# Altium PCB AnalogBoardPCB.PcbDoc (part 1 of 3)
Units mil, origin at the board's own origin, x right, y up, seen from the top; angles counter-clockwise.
Board outline 5875 x 2550 mil, 4 copper layers (Top Layer, GND, VCC, Bottom Layer); 569 components, 22 nets, 1336 pads, 360 vias.
Unrouted connection lines stored in the file: 31.
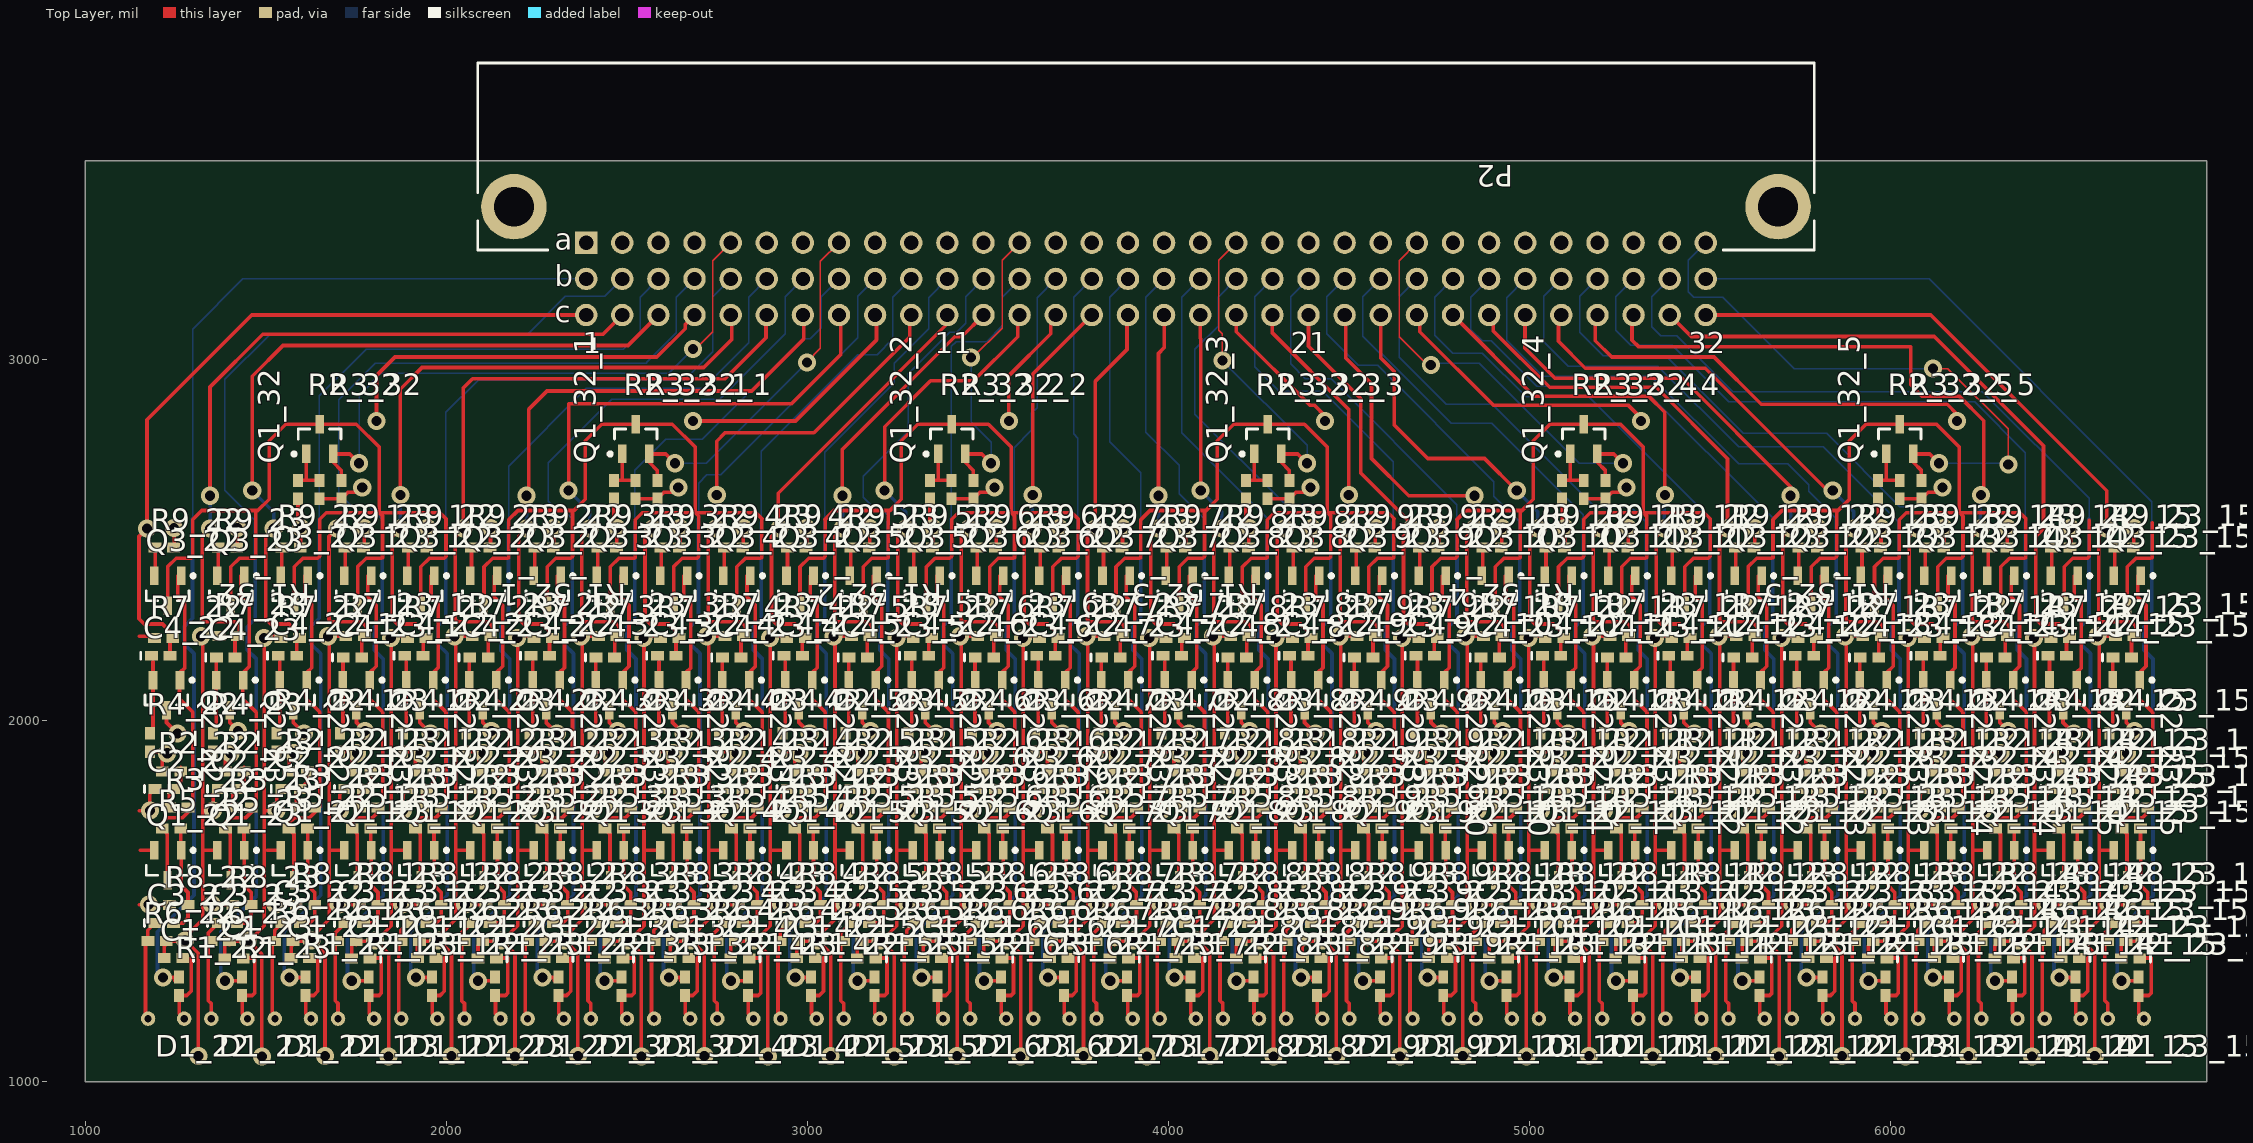
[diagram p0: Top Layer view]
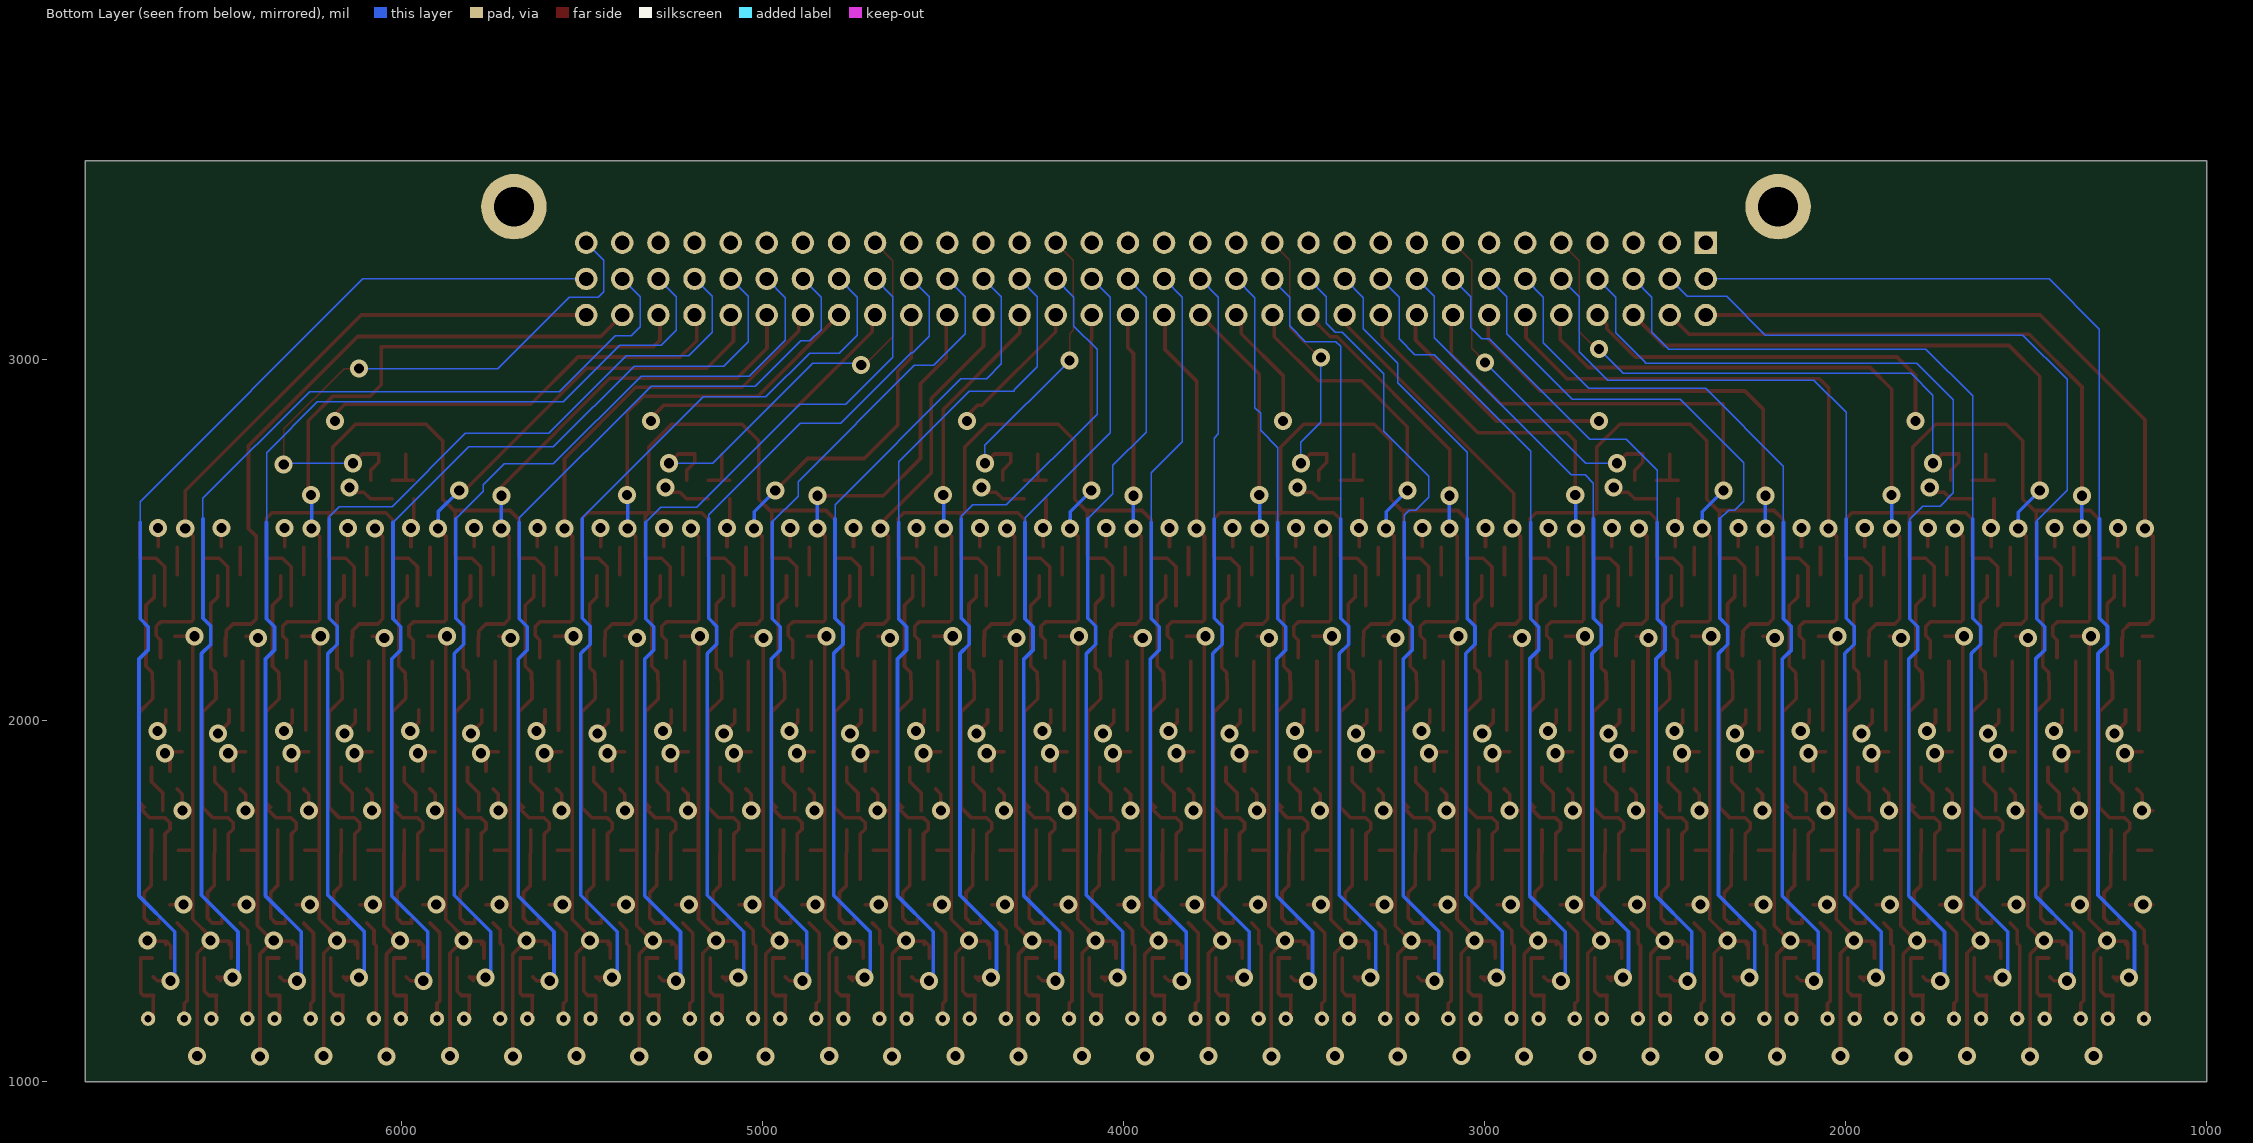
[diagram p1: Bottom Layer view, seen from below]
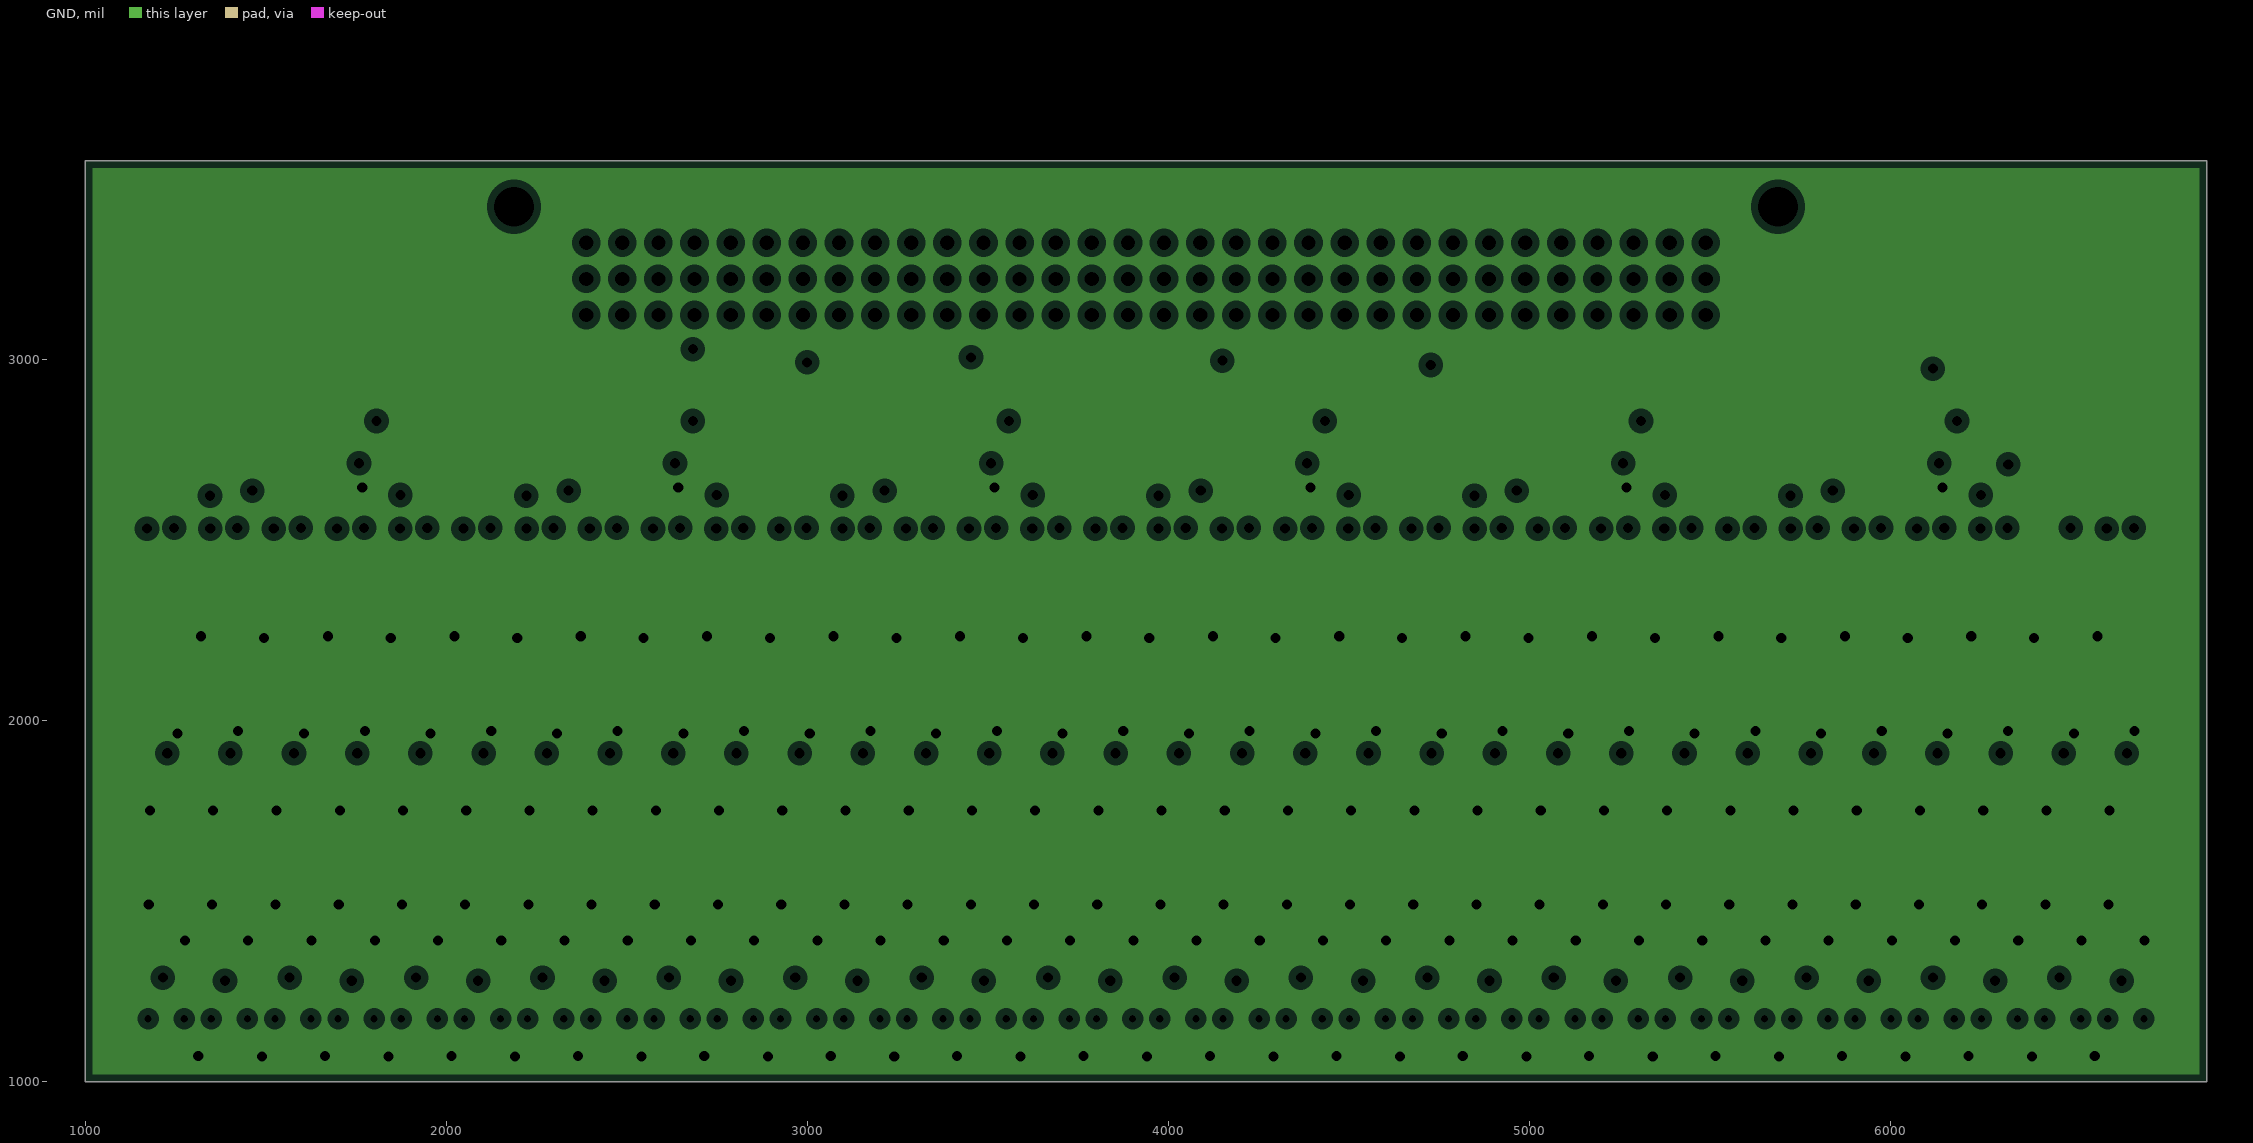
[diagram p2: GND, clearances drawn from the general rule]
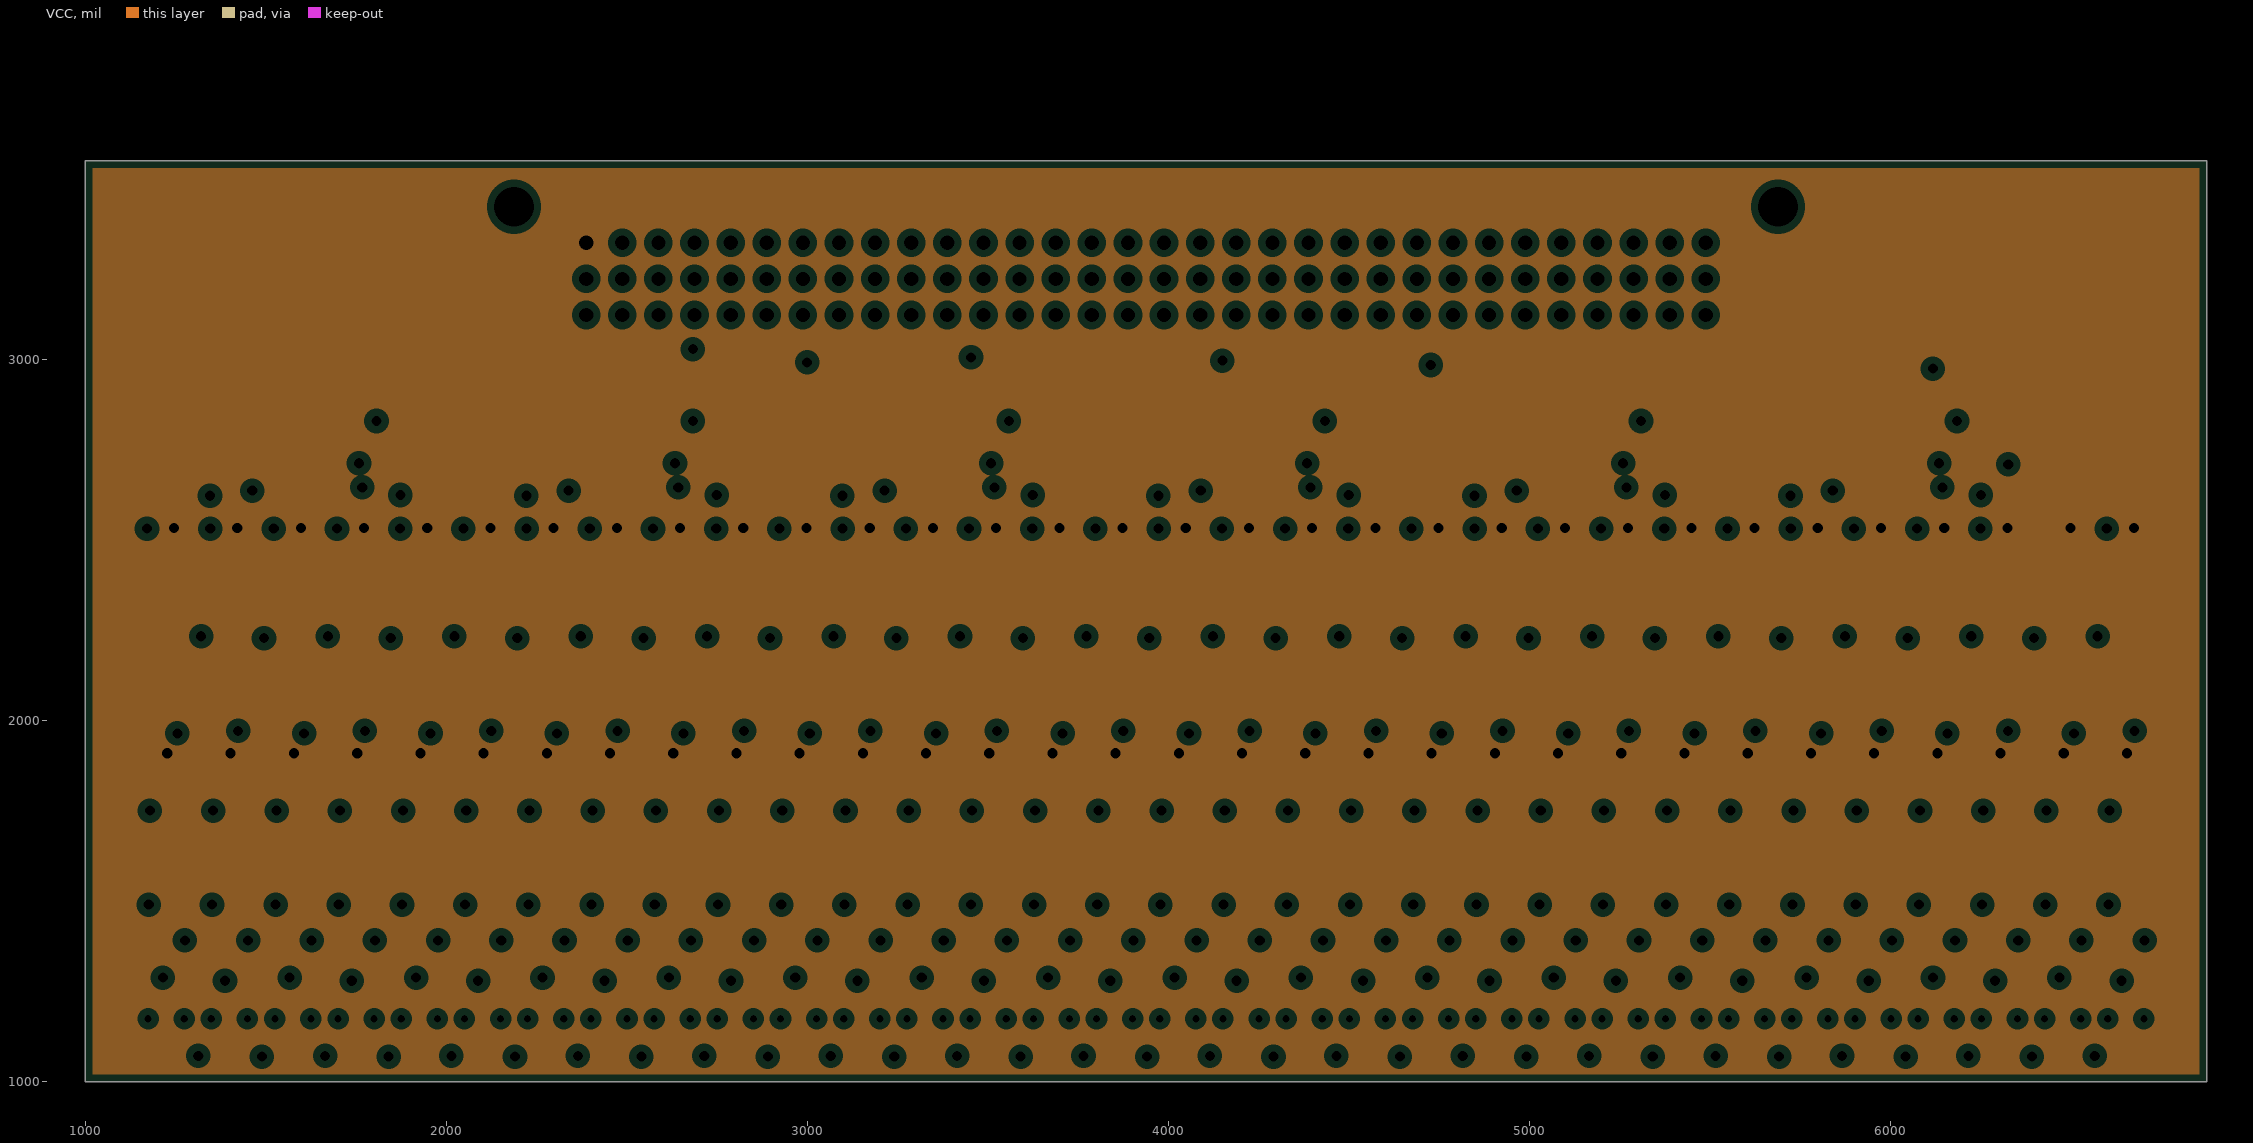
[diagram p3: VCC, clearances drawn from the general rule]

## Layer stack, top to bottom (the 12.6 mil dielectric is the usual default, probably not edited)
Top Layer: signal copper 1.4
Dielectric: core 12.6, FR-4, Dk 4.8
GND: plane copper 1.4, net GND
Dielectric: prepreg 12.6, FR-4, Dk 4.8
VCC: plane copper 1.4, net VCC
Dielectric: core 12.6, FR-4, Dk 4.8
Bottom Layer: signal copper 1.4

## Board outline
1000,1000 6875,1000 6875,3550 1000,3550

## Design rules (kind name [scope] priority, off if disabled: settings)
Clearance biasvoltages [InNet('SIPMBIAS1')] p1: gap=15
Clearance [All] p2: gap=10
ComponentClearance [All] p1: gap=10 collisioncheckmode=3 verticalgap=10
PlaneClearance [All] p1: clearance=20
PlaneConnect [All] p1: planeconnectstyle=Relief reliefexpansion=20 reliefentries=4 reliefconductorwidth=10 reliefairgap=10
PolygonConnect [All] p1: connectstyle=Relief reliefconductorwidth=10 reliefentries=4 polygonreliefangle="90 Angle"
RoutingVias [All] p1: holewidth=28 width=50 viastyle="Through Hole" minholewidth=28 minwidth=50 maxholewidth=28 maxwidth=50
ShortCircuit ShortCircuitEurocard [InComponent(P2)] p1: allowed=TRUE
ShortCircuit [All] p2: allowed=FALSE
SolderMaskExpansion [All] p1: expansion=4
TestPointUsage [All] p1: valid=0 allowmultiple=FALSE
Testpoint [All] p1: side=15 testpointundercomponent=TRUE minsize=40 maxsize=100 preferedsize=60 minholesize=0 maxholesize=40 preferedholesize=32 testpointgrid=1 style=1023 order=0-112345678
Width [All] p1: maxlimit=10 minlimit=1 preferedwidth=4
15 further rules are at their usual default settings.

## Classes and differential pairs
component class Amplifier1: C1 C2 C3 C4 D1 Q1 Q2 Q3 R1 R2 R3 R4 R5 R6 R7 R8 R9

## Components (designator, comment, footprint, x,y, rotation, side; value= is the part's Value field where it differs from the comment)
C1_22 "Cap" 0402 1245.09,1342 r180 top (schematic designator C1)
C1_22_1 "Cap" 0402 1596.09,1342 r180 top (schematic designator C1)
C1_22_2 "Cap" 0402 1946.09,1342 r180 top (schematic designator C1)
C1_22_3 "Cap" 0402 2296.09,1342 r180 top (schematic designator C1)
C1_22_4 "Cap" 0402 2646.09,1342 r180 top (schematic designator C1)
C1_22_5 "Cap" 0402 2996.09,1342 r180 top (schematic designator C1)
C1_22_6 "Cap" 0402 3346.09,1342 r180 top (schematic designator C1)
C1_22_7 "Cap" 0402 3696.09,1342 r180 top (schematic designator C1)
C1_22_8 "Cap" 0402 4046.09,1342 r180 top (schematic designator C1)
C1_22_9 "Cap" 0402 4396.09,1342 r180 top (schematic designator C1)
C1_22_10 "Cap" 0402 4746.09,1342 r180 top (schematic designator C1)
C1_22_11 "Cap" 0402 5096.09,1342 r180 top (schematic designator C1)
C1_22_12 "Cap" 0402 5446.09,1342 r180 top (schematic designator C1)
C1_22_13 "Cap" 0402 5796.09,1342 r180 top (schematic designator C1)
C1_22_14 "Cap" 0402 6146.09,1342 r180 top (schematic designator C1)
C1_22_15 "Cap" 0402 6496.09,1342 r180 top (schematic designator C1)
C1_23 "Cap" 0402 1412.5,1341 r180 top (schematic designator C1)
C1_23_1 "Cap" 0402 1763.5,1341 r180 top (schematic designator C1)
C1_23_2 "Cap" 0402 2113.5,1341 r180 top (schematic designator C1)
C1_23_3 "Cap" 0402 2463.5,1341 r180 top (schematic designator C1)
C1_23_4 "Cap" 0402 2813.5,1341 r180 top (schematic designator C1)
C1_23_5 "Cap" 0402 3163.5,1341 r180 top (schematic designator C1)
C1_23_6 "Cap" 0402 3513.5,1341 r180 top (schematic designator C1)
C1_23_7 "Cap" 0402 3863.5,1341 r180 top (schematic designator C1)
C1_23_8 "Cap" 0402 4213.5,1341 r180 top (schematic designator C1)
C1_23_9 "Cap" 0402 4563.5,1341 r180 top (schematic designator C1)
C1_23_10 "Cap" 0402 4913.5,1341 r180 top (schematic designator C1)
C1_23_11 "Cap" 0402 5263.5,1341 r180 top (schematic designator C1)
C1_23_12 "Cap" 0402 5613.5,1341 r180 top (schematic designator C1)
C1_23_13 "Cap" 0402 5963.5,1341 r180 top (schematic designator C1)
C1_23_14 "Cap" 0402 6313.5,1341 r180 top (schematic designator C1)
C1_23_15 "Cap" 0402 6663.5,1341 r180 top (schematic designator C1)
C2_22 "Cap" 0402 1219.5,1810 r0 top (schematic designator C2)
C2_22_1 "Cap" 0402 1570.5,1810 r0 top (schematic designator C2)
C2_22_2 "Cap" 0402 1920.5,1810 r0 top (schematic designator C2)
C2_22_3 "Cap" 0402 2270.5,1810 r0 top (schematic designator C2)
C2_22_4 "Cap" 0402 2620.5,1810 r0 top (schematic designator C2)
C2_22_5 "Cap" 0402 2970.5,1810 r0 top (schematic designator C2)
C2_22_6 "Cap" 0402 3320.5,1810 r0 top (schematic designator C2)
C2_22_7 "Cap" 0402 3670.5,1810 r0 top (schematic designator C2)
C2_22_8 "Cap" 0402 4020.5,1810 r0 top (schematic designator C2)
C2_22_9 "Cap" 0402 4370.5,1810 r0 top (schematic designator C2)
C2_22_10 "Cap" 0402 4720.5,1810 r0 top (schematic designator C2)
C2_22_11 "Cap" 0402 5070.5,1810 r0 top (schematic designator C2)
C2_22_12 "Cap" 0402 5420.5,1810 r0 top (schematic designator C2)
C2_22_13 "Cap" 0402 5770.5,1810 r0 top (schematic designator C2)
C2_22_14 "Cap" 0402 6120.5,1810 r0 top (schematic designator C2)
C2_22_15 "Cap" 0402 6470.5,1810 r0 top (schematic designator C2)
C2_23 "Cap" 0402 1394.5,1810 r0 top (schematic designator C2)
C2_23_1 "Cap" 0402 1745.5,1810 r0 top (schematic designator C2)
C2_23_2 "Cap" 0402 2095.5,1810 r0 top (schematic designator C2)
C2_23_3 "Cap" 0402 2445.5,1810 r0 top (schematic designator C2)
C2_23_4 "Cap" 0402 2795.5,1810 r0 top (schematic designator C2)
C2_23_5 "Cap" 0402 3145.5,1810 r0 top (schematic designator C2)
C2_23_6 "Cap" 0402 3495.5,1810 r0 top (schematic designator C2)
C2_23_7 "Cap" 0402 3845.5,1810 r0 top (schematic designator C2)
C2_23_8 "Cap" 0402 4195.5,1810 r0 top (schematic designator C2)
C2_23_9 "Cap" 0402 4545.5,1810 r0 top (schematic designator C2)
C2_23_10 "Cap" 0402 4895.5,1810 r0 top (schematic designator C2)
C2_23_11 "Cap" 0402 5245.5,1810 r0 top (schematic designator C2)
C2_23_12 "Cap" 0402 5595.5,1810 r0 top (schematic designator C2)
C2_23_13 "Cap" 0402 5945.5,1810 r0 top (schematic designator C2)
C2_23_14 "Cap" 0402 6295.5,1810 r0 top (schematic designator C2)
C2_23_15 "Cap" 0402 6645.5,1810 r0 top (schematic designator C2)
C3_22 "Cap" 0402 1219.5,1439 r0 top (schematic designator C3)
C3_22_1 "Cap" 0402 1570.5,1439 r0 top (schematic designator C3)
C3_22_2 "Cap" 0402 1920.5,1439 r0 top (schematic designator C3)
C3_22_3 "Cap" 0402 2270.5,1439 r0 top (schematic designator C3)
C3_22_4 "Cap" 0402 2620.5,1439 r0 top (schematic designator C3)
C3_22_5 "Cap" 0402 2970.5,1439 r0 top (schematic designator C3)
C3_22_6 "Cap" 0402 3320.5,1439 r0 top (schematic designator C3)
C3_22_7 "Cap" 0402 3670.5,1439 r0 top (schematic designator C3)
C3_22_8 "Cap" 0402 4020.5,1439 r0 top (schematic designator C3)
C3_22_9 "Cap" 0402 4370.5,1439 r0 top (schematic designator C3)
C3_22_10 "Cap" 0402 4720.5,1439 r0 top (schematic designator C3)
C3_22_11 "Cap" 0402 5070.5,1439 r0 top (schematic designator C3)
C3_22_12 "Cap" 0402 5420.5,1439 r0 top (schematic designator C3)
C3_22_13 "Cap" 0402 5770.5,1439 r0 top (schematic designator C3)
C3_22_14 "Cap" 0402 6120.5,1439 r0 top (schematic designator C3)
C3_22_15 "Cap" 0402 6470.5,1439 r0 top (schematic designator C3)
C3_23 "Cap" 0402 1394.5,1439 r0 top (schematic designator C3)
C3_23_1 "Cap" 0402 1745.5,1439 r0 top (schematic designator C3)
C3_23_2 "Cap" 0402 2095.5,1439 r0 top (schematic designator C3)
C3_23_3 "Cap" 0402 2445.5,1439 r0 top (schematic designator C3)
C3_23_4 "Cap" 0402 2795.5,1439 r0 top (schematic designator C3)
C3_23_5 "Cap" 0402 3145.5,1439 r0 top (schematic designator C3)
C3_23_6 "Cap" 0402 3495.5,1439 r0 top (schematic designator C3)
C3_23_7 "Cap" 0402 3845.5,1439 r0 top (schematic designator C3)
C3_23_8 "Cap" 0402 4195.5,1439 r0 top (schematic designator C3)
C3_23_9 "Cap" 0402 4545.5,1439 r0 top (schematic designator C3)
C3_23_10 "Cap" 0402 4895.5,1439 r0 top (schematic designator C3)
C3_23_11 "Cap" 0402 5245.5,1439 r0 top (schematic designator C3)
C3_23_12 "Cap" 0402 5595.5,1439 r0 top (schematic designator C3)
C3_23_13 "Cap" 0402 5945.5,1439 r0 top (schematic designator C3)
C3_23_14 "Cap" 0402 6295.5,1439 r0 top (schematic designator C3)
C3_23_15 "Cap" 0402 6645.5,1439 r0 top (schematic designator C3)
C4_22 "Cap" 0402 1209.5,2179 r0 top (schematic designator C4)
C4_22_1 "Cap" 0402 1560.5,2179 r0 top (schematic designator C4)
C4_22_2 "Cap" 0402 1910.5,2179 r0 top (schematic designator C4)
C4_22_3 "Cap" 0402 2260.5,2179 r0 top (schematic designator C4)
C4_22_4 "Cap" 0402 2610.5,2179 r0 top (schematic designator C4)
C4_22_5 "Cap" 0402 2960.5,2179 r0 top (schematic designator C4)
C4_22_6 "Cap" 0402 3310.5,2179 r0 top (schematic designator C4)
C4_22_7 "Cap" 0402 3660.5,2179 r0 top (schematic designator C4)
C4_22_8 "Cap" 0402 4010.5,2179 r0 top (schematic designator C4)
C4_22_9 "Cap" 0402 4360.5,2179 r0 top (schematic designator C4)
C4_22_10 "Cap" 0402 4710.5,2179 r0 top (schematic designator C4)
C4_22_11 "Cap" 0402 5060.5,2179 r0 top (schematic designator C4)
C4_22_12 "Cap" 0402 5410.5,2179 r0 top (schematic designator C4)
C4_22_13 "Cap" 0402 5760.5,2179 r0 top (schematic designator C4)
C4_22_14 "Cap" 0402 6110.5,2179 r0 top (schematic designator C4)
C4_22_15 "Cap" 0402 6460.5,2179 r0 top (schematic designator C4)
C4_23 "Cap" 0402 1389.5,2174 r0 top (schematic designator C4)
C4_23_1 "Cap" 0402 1740.5,2174 r0 top (schematic designator C4)
C4_23_2 "Cap" 0402 2090.5,2174 r0 top (schematic designator C4)
C4_23_3 "Cap" 0402 2440.5,2174 r0 top (schematic designator C4)
C4_23_4 "Cap" 0402 2790.5,2174 r0 top (schematic designator C4)
C4_23_5 "Cap" 0402 3140.5,2174 r0 top (schematic designator C4)
C4_23_6 "Cap" 0402 3490.5,2174 r0 top (schematic designator C4)
C4_23_7 "Cap" 0402 3840.5,2174 r0 top (schematic designator C4)
C4_23_8 "Cap" 0402 4190.5,2174 r0 top (schematic designator C4)
C4_23_9 "Cap" 0402 4540.5,2174 r0 top (schematic designator C4)
C4_23_10 "Cap" 0402 4890.5,2174 r0 top (schematic designator C4)
C4_23_11 "Cap" 0402 5240.5,2174 r0 top (schematic designator C4)
C4_23_12 "Cap" 0402 5590.5,2174 r0 top (schematic designator C4)
C4_23_13 "Cap" 0402 5940.5,2174 r0 top (schematic designator C4)
C4_23_14 "Cap" 0402 6290.5,2174 r0 top (schematic designator C4)
C4_23_15 "Cap" 0402 6640.5,2174 r0 top (schematic designator C4)
D1_22 "SiPM" "Photonique SiPM" 1224.5,1124 r0 top (schematic designator D1)
D1_22_1 "SiPM" "Photonique SiPM" 1575.5,1124 r0 top (schematic designator D1)
D1_22_2 "SiPM" "Photonique SiPM" 1925.5,1124 r0 top (schematic designator D1)
D1_22_3 "SiPM" "Photonique SiPM" 2275.5,1124 r0 top (schematic designator D1)
D1_22_4 "SiPM" "Photonique SiPM" 2625.5,1124 r0 top (schematic designator D1)
D1_22_5 "SiPM" "Photonique SiPM" 2975.5,1124 r0 top (schematic designator D1)
D1_22_6 "SiPM" "Photonique SiPM" 3325.5,1124 r0 top (schematic designator D1)
D1_22_7 "SiPM" "Photonique SiPM" 3675.5,1124 r0 top (schematic designator D1)
D1_22_8 "SiPM" "Photonique SiPM" 4025.5,1124 r0 top (schematic designator D1)
D1_22_9 "SiPM" "Photonique SiPM" 4375.5,1124 r0 top (schematic designator D1)
D1_22_10 "SiPM" "Photonique SiPM" 4725.5,1124 r0 top (schematic designator D1)
D1_22_11 "SiPM" "Photonique SiPM" 5075.5,1124 r0 top (schematic designator D1)
D1_22_12 "SiPM" "Photonique SiPM" 5425.5,1124 r0 top (schematic designator D1)
D1_22_13 "SiPM" "Photonique SiPM" 5775.5,1124 r0 top (schematic designator D1)
D1_22_14 "SiPM" "Photonique SiPM" 6125.5,1124 r0 top (schematic designator D1)
D1_22_15 "SiPM" "Photonique SiPM" 6475.5,1124 r0 top (schematic designator D1)
D1_23 "SiPM" "Photonique SiPM" 1399.5,1124 r0 top (schematic designator D1)
D1_23_1 "SiPM" "Photonique SiPM" 1750.5,1124 r0 top (schematic designator D1)
D1_23_2 "SiPM" "Photonique SiPM" 2100.5,1124 r0 top (schematic designator D1)
D1_23_3 "SiPM" "Photonique SiPM" 2450.5,1124 r0 top (schematic designator D1)
D1_23_4 "SiPM" "Photonique SiPM" 2800.5,1124 r0 top (schematic designator D1)
D1_23_5 "SiPM" "Photonique SiPM" 3150.5,1124 r0 top (schematic designator D1)
D1_23_6 "SiPM" "Photonique SiPM" 3500.5,1124 r0 top (schematic designator D1)
D1_23_7 "SiPM" "Photonique SiPM" 3850.5,1124 r0 top (schematic designator D1)
D1_23_8 "SiPM" "Photonique SiPM" 4200.5,1124 r0 top (schematic designator D1)
D1_23_9 "SiPM" "Photonique SiPM" 4550.5,1124 r0 top (schematic designator D1)
D1_23_10 "SiPM" "Photonique SiPM" 4900.5,1124 r0 top (schematic designator D1)
D1_23_11 "SiPM" "Photonique SiPM" 5250.5,1124 r0 top (schematic designator D1)
D1_23_12 "SiPM" "Photonique SiPM" 5600.5,1124 r0 top (schematic designator D1)
D1_23_13 "SiPM" "Photonique SiPM" 5950.5,1124 r0 top (schematic designator D1)
D1_23_14 "SiPM" "Photonique SiPM" 6300.5,1124 r0 top (schematic designator D1)
D1_23_15 "SiPM" "Photonique SiPM" 6650.5,1124 r0 top (schematic designator D1)
P2 "DIN41612 48 Connector" EURO2.54-2H96 3937.5,3820 r0 top
Q1_22 "BFS17A" SOT23_N 1228.5,1599 r270 top (schematic designator Q1)
Q1_22_1 "BFS17A" SOT23_N 1579.5,1599 r270 top (schematic designator Q1)
Q1_22_2 "BFS17A" SOT23_N 1929.5,1599 r270 top (schematic designator Q1)
Q1_22_3 "BFS17A" SOT23_N 2279.5,1599 r270 top (schematic designator Q1)
Q1_22_4 "BFS17A" SOT23_N 2629.5,1599 r270 top (schematic designator Q1)
Q1_22_5 "BFS17A" SOT23_N 2979.5,1599 r270 top (schematic designator Q1)
Q1_22_6 "BFS17A" SOT23_N 3329.5,1599 r270 top (schematic designator Q1)
Q1_22_7 "BFS17A" SOT23_N 3679.5,1599 r270 top (schematic designator Q1)
Q1_22_8 "BFS17A" SOT23_N 4029.5,1599 r270 top (schematic designator Q1)
Q1_22_9 "BFS17A" SOT23_N 4379.5,1599 r270 top (schematic designator Q1)
Q1_22_10 "BFS17A" SOT23_N 4729.5,1599 r270 top (schematic designator Q1)
Q1_22_11 "BFS17A" SOT23_N 5079.5,1599 r270 top (schematic designator Q1)
Q1_22_12 "BFS17A" SOT23_N 5429.5,1599 r270 top (schematic designator Q1)
Q1_22_13 "BFS17A" SOT23_N 5779.5,1599 r270 top (schematic designator Q1)
Q1_22_14 "BFS17A" SOT23_N 6129.5,1599 r270 top (schematic designator Q1)
Q1_22_15 "BFS17A" SOT23_N 6479.5,1599 r270 top (schematic designator Q1)
Q1_23 "BFS17A" SOT23_N 1403.5,1599 r270 top (schematic designator Q1)
Q1_23_1 "BFS17A" SOT23_N 1754.5,1599 r270 top (schematic designator Q1)
Q1_23_2 "BFS17A" SOT23_N 2104.5,1599 r270 top (schematic designator Q1)
Q1_23_3 "BFS17A" SOT23_N 2454.5,1599 r270 top (schematic designator Q1)
Q1_23_4 "BFS17A" SOT23_N 2804.5,1599 r270 top (schematic designator Q1)
Q1_23_5 "BFS17A" SOT23_N 3154.5,1599 r270 top (schematic designator Q1)
Q1_23_6 "BFS17A" SOT23_N 3504.5,1599 r270 top (schematic designator Q1)
Q1_23_7 "BFS17A" SOT23_N 3854.5,1599 r270 top (schematic designator Q1)
Q1_23_8 "BFS17A" SOT23_N 4204.5,1599 r270 top (schematic designator Q1)
Q1_23_9 "BFS17A" SOT23_N 4554.5,1599 r270 top (schematic designator Q1)
Q1_23_10 "BFS17A" SOT23_N 4904.5,1599 r270 top (schematic designator Q1)
Q1_23_11 "BFS17A" SOT23_N 5254.5,1599 r270 top (schematic designator Q1)
Q1_23_12 "BFS17A" SOT23_N 5604.5,1599 r270 top (schematic designator Q1)
Q1_23_13 "BFS17A" SOT23_N 5954.5,1599 r270 top (schematic designator Q1)
Q1_23_14 "BFS17A" SOT23_N 6304.5,1599 r270 top (schematic designator Q1)
Q1_23_15 "BFS17A" SOT23_N 6654.5,1599 r270 top (schematic designator Q1)
Q1_32 "BFS17A" SOT23_N 1649.5,2779 r90 top (schematic designator Q1)
Q1_32_1 "BFS17A" SOT23_N 2524.5,2779 r90 top (schematic designator Q1)
Q1_32_2 "BFS17A" SOT23_N 3399.5,2779 r90 top (schematic designator Q1)
Q1_32_3 "BFS17A" SOT23_N 4274.5,2779 r90 top (schematic designator Q1)
Q1_32_4 "BFS17A" SOT23_N 5149.5,2779 r90 top (schematic designator Q1)
Q1_32_5 "BFS17A" SOT23_N 6024.5,2779 r90 top (schematic designator Q1)
Q2_22 "BFT92" SOT23_N 1225.5,2070 r270 top (schematic designator Q2)
Q2_22_1 "BFT92" SOT23_N 1576.5,2070 r270 top (schematic designator Q2)
Q2_22_2 "BFT92" SOT23_N 1926.5,2070 r270 top (schematic designator Q2)
Q2_22_3 "BFT92" SOT23_N 2276.5,2070 r270 top (schematic designator Q2)
Q2_22_4 "BFT92" SOT23_N 2626.5,2070 r270 top (schematic designator Q2)
Q2_22_5 "BFT92" SOT23_N 2976.5,2070 r270 top (schematic designator Q2)
Q2_22_6 "BFT92" SOT23_N 3326.5,2070 r270 top (schematic designator Q2)
Q2_22_7 "BFT92" SOT23_N 3676.5,2070 r270 top (schematic designator Q2)
Q2_22_8 "BFT92" SOT23_N 4026.5,2070 r270 top (schematic designator Q2)
Q2_22_9 "BFT92" SOT23_N 4376.5,2070 r270 top (schematic designator Q2)
Q2_22_10 "BFT92" SOT23_N 4726.5,2070 r270 top (schematic designator Q2)
Q2_22_11 "BFT92" SOT23_N 5076.5,2070 r270 top (schematic designator Q2)
Q2_22_12 "BFT92" SOT23_N 5426.5,2070 r270 top (schematic designator Q2)
Q2_22_13 "BFT92" SOT23_N 5776.5,2070 r270 top (schematic designator Q2)
Q2_22_14 "BFT92" SOT23_N 6126.5,2070 r270 top (schematic designator Q2)
Q2_22_15 "BFT92" SOT23_N 6476.5,2070 r270 top (schematic designator Q2)
Q2_23 "BFT92" SOT23_N 1400.5,2070 r270 top (schematic designator Q2)
Q2_23_1 "BFT92" SOT23_N 1751.5,2070 r270 top (schematic designator Q2)
Q2_23_2 "BFT92" SOT23_N 2101.5,2070 r270 top (schematic designator Q2)
Q2_23_3 "BFT92" SOT23_N 2451.5,2070 r270 top (schematic designator Q2)
Q2_23_4 "BFT92" SOT23_N 2801.5,2070 r270 top (schematic designator Q2)
Q2_23_5 "BFT92" SOT23_N 3151.5,2070 r270 top (schematic designator Q2)
Q2_23_6 "BFT92" SOT23_N 3501.5,2070 r270 top (schematic designator Q2)
Q2_23_7 "BFT92" SOT23_N 3851.5,2070 r270 top (schematic designator Q2)
Q2_23_8 "BFT92" SOT23_N 4201.5,2070 r270 top (schematic designator Q2)
Q2_23_9 "BFT92" SOT23_N 4551.5,2070 r270 top (schematic designator Q2)
Q2_23_10 "BFT92" SOT23_N 4901.5,2070 r270 top (schematic designator Q2)
Q2_23_11 "BFT92" SOT23_N 5251.5,2070 r270 top (schematic designator Q2)
Q2_23_12 "BFT92" SOT23_N 5601.5,2070 r270 top (schematic designator Q2)
Q2_23_13 "BFT92" SOT23_N 5951.5,2070 r270 top (schematic designator Q2)
Q2_23_14 "BFT92" SOT23_N 6301.5,2070 r270 top (schematic designator Q2)
Q2_23_15 "BFT92" SOT23_N 6651.5,2070 r270 top (schematic designator Q2)
Q3_22 "BFT92" SOT23_N 1228.5,2359 r270 top (schematic designator Q3)
Q3_22_1 "BFT92" SOT23_N 1579.5,2359 r270 top (schematic designator Q3)
Q3_22_2 "BFT92" SOT23_N 1929.5,2359 r270 top (schematic designator Q3)
Q3_22_3 "BFT92" SOT23_N 2279.5,2359 r270 top (schematic designator Q3)
Q3_22_4 "BFT92" SOT23_N 2629.5,2359 r270 top (schematic designator Q3)
Q3_22_5 "BFT92" SOT23_N 2979.5,2359 r270 top (schematic designator Q3)
Q3_22_6 "BFT92" SOT23_N 3329.5,2359 r270 top (schematic designator Q3)
Q3_22_7 "BFT92" SOT23_N 3679.5,2359 r270 top (schematic designator Q3)
Q3_22_8 "BFT92" SOT23_N 4029.5,2359 r270 top (schematic designator Q3)
Q3_22_9 "BFT92" SOT23_N 4379.5,2359 r270 top (schematic designator Q3)
Q3_22_10 "BFT92" SOT23_N 4729.5,2359 r270 top (schematic designator Q3)
Q3_22_11 "BFT92" SOT23_N 5079.5,2359 r270 top (schematic designator Q3)
Q3_22_12 "BFT92" SOT23_N 5429.5,2359 r270 top (schematic designator Q3)
Q3_22_13 "BFT92" SOT23_N 5779.5,2359 r270 top (schematic designator Q3)
Q3_22_14 "BFT92" SOT23_N 6129.5,2359 r270 top (schematic designator Q3)
Q3_22_15 "BFT92" SOT23_N 6479.5,2359 r270 top (schematic designator Q3)
Q3_23 "BFT92" SOT23_N 1403.5,2359 r270 top (schematic designator Q3)
Q3_23_1 "BFT92" SOT23_N 1754.5,2359 r270 top (schematic designator Q3)
Q3_23_2 "BFT92" SOT23_N 2104.5,2359 r270 top (schematic designator Q3)
Q3_23_3 "BFT92" SOT23_N 2454.5,2359 r270 top (schematic designator Q3)
Q3_23_4 "BFT92" SOT23_N 2804.5,2359 r270 top (schematic designator Q3)
Q3_23_5 "BFT92" SOT23_N 3154.5,2359 r270 top (schematic designator Q3)
Q3_23_6 "BFT92" SOT23_N 3504.5,2359 r270 top (schematic designator Q3)
Q3_23_7 "BFT92" SOT23_N 3854.5,2359 r270 top (schematic designator Q3)
Q3_23_8 "BFT92" SOT23_N 4204.5,2359 r270 top (schematic designator Q3)
Q3_23_9 "BFT92" SOT23_N 4554.5,2359 r270 top (schematic designator Q3)
Q3_23_10 "BFT92" SOT23_N 4904.5,2359 r270 top (schematic designator Q3)
Q3_23_11 "BFT92" SOT23_N 5254.5,2359 r270 top (schematic designator Q3)
Q3_23_12 "BFT92" SOT23_N 5604.5,2359 r270 top (schematic designator Q3)
Q3_23_13 "BFT92" SOT23_N 5954.5,2359 r270 top (schematic designator Q3)
Q3_23_14 "BFT92" SOT23_N 6304.5,2359 r270 top (schematic designator Q3)
Q3_23_15 "BFT92" SOT23_N 6654.5,2359 r270 top (schematic designator Q3)
R1_22 "Res2" 1005[0402] 1259.5,1264 r270 top (schematic designator R1)
R1_22_1 "Res2" 1005[0402] 1610.5,1264 r270 top (schematic designator R1)
R1_22_2 "Res2" 1005[0402] 1960.5,1264 r270 top (schematic designator R1)
R1_22_3 "Res2" 1005[0402] 2310.5,1264 r270 top (schematic designator R1)
R1_22_4 "Res2" 1005[0402] 2660.5,1264 r270 top (schematic designator R1)
R1_22_5 "Res2" 1005[0402] 3010.5,1264 r270 top (schematic designator R1)
R1_22_6 "Res2" 1005[0402] 3360.5,1264 r270 top (schematic designator R1)
R1_22_7 "Res2" 1005[0402] 3710.5,1264 r270 top (schematic designator R1)
R1_22_8 "Res2" 1005[0402] 4060.5,1264 r270 top (schematic designator R1)
R1_22_9 "Res2" 1005[0402] 4410.5,1264 r270 top (schematic designator R1)
R1_22_10 "Res2" 1005[0402] 4760.5,1264 r270 top (schematic designator R1)
R1_22_11 "Res2" 1005[0402] 5110.5,1264 r270 top (schematic designator R1)
R1_22_12 "Res2" 1005[0402] 5460.5,1264 r270 top (schematic designator R1)
R1_22_13 "Res2" 1005[0402] 5810.5,1264 r270 top (schematic designator R1)
R1_22_14 "Res2" 1005[0402] 6160.5,1264 r270 top (schematic designator R1)
R1_22_15 "Res2" 1005[0402] 6510.5,1264 r270 top (schematic designator R1)
R1_23 "Res2" 1005[0402] 1434.5,1264 r270 top (schematic designator R1)
R1_23_1 "Res2" 1005[0402] 1785.5,1264 r270 top (schematic designator R1)
R1_23_2 "Res2" 1005[0402] 2135.5,1264 r270 top (schematic designator R1)
R1_23_3 "Res2" 1005[0402] 2485.5,1264 r270 top (schematic designator R1)
R1_23_4 "Res2" 1005[0402] 2835.5,1264 r270 top (schematic designator R1)
R1_23_5 "Res2" 1005[0402] 3185.5,1264 r270 top (schematic designator R1)
R1_23_6 "Res2" 1005[0402] 3535.5,1264 r270 top (schematic designator R1)
R1_23_7 "Res2" 1005[0402] 3885.5,1264 r270 top (schematic designator R1)
R1_23_8 "Res2" 1005[0402] 4235.5,1264 r270 top (schematic designator R1)
R1_23_9 "Res2" 1005[0402] 4585.5,1264 r270 top (schematic designator R1)
R1_23_10 "Res2" 1005[0402] 4935.5,1264 r270 top (schematic designator R1)
R1_23_11 "Res2" 1005[0402] 5285.5,1264 r270 top (schematic designator R1)
R1_23_12 "Res2" 1005[0402] 5635.5,1264 r270 top (schematic designator R1)
R1_23_13 "Res2" 1005[0402] 5985.5,1264 r270 top (schematic designator R1)
R1_23_14 "Res2" 1005[0402] 6335.5,1264 r270 top (schematic designator R1)
R1_23_15 "Res2" 1005[0402] 6685.5,1264 r270 top (schematic designator R1)
R1_32 "Res2" 1005[0402] 1589.5,2639 r270 top (schematic designator R1)
R1_32_1 "Res2" 1005[0402] 2464.5,2639 r270 top (schematic designator R1)
R1_32_2 "Res2" 1005[0402] 3339.5,2639 r270 top (schematic designator R1)
R1_32_3 "Res2" 1005[0402] 4214.5,2639 r270 top (schematic designator R1)
R1_32_4 "Res2" 1005[0402] 5089.5,2639 r270 top (schematic designator R1)
R1_32_5 "Res2" 1005[0402] 5964.5,2639 r270 top (schematic designator R1)
R2_22 "Res2" 1005[0402] 1239.5,1859 r180 top (schematic designator R2)
R2_22_1 "Res2" 1005[0402] 1590.5,1859 r180 top (schematic designator R2)
R2_22_2 "Res2" 1005[0402] 1940.5,1859 r180 top (schematic designator R2)
R2_22_3 "Res2" 1005[0402] 2290.5,1859 r180 top (schematic designator R2)
R2_22_4 "Res2" 1005[0402] 2640.5,1859 r180 top (schematic designator R2)
R2_22_5 "Res2" 1005[0402] 2990.5,1859 r180 top (schematic designator R2)
R2_22_6 "Res2" 1005[0402] 3340.5,1859 r180 top (schematic designator R2)
R2_22_7 "Res2" 1005[0402] 3690.5,1859 r180 top (schematic designator R2)
R2_22_8 "Res2" 1005[0402] 4040.5,1859 r180 top (schematic designator R2)
R2_22_9 "Res2" 1005[0402] 4390.5,1859 r180 top (schematic designator R2)
R2_22_10 "Res2" 1005[0402] 4740.5,1859 r180 top (schematic designator R2)
R2_22_11 "Res2" 1005[0402] 5090.5,1859 r180 top (schematic designator R2)
R2_22_12 "Res2" 1005[0402] 5440.5,1859 r180 top (schematic designator R2)
R2_22_13 "Res2" 1005[0402] 5790.5,1859 r180 top (schematic designator R2)
R2_22_14 "Res2" 1005[0402] 6140.5,1859 r180 top (schematic designator R2)
R2_22_15 "Res2" 1005[0402] 6490.5,1859 r180 top (schematic designator R2)
R2_23 "Res2" 1005[0402] 1414.5,1859 r180 top (schematic designator R2)
R2_23_1 "Res2" 1005[0402] 1765.5,1859 r180 top (schematic designator R2)
R2_23_2 "Res2" 1005[0402] 2115.5,1859 r180 top (schematic designator R2)
R2_23_3 "Res2" 1005[0402] 2465.5,1859 r180 top (schematic designator R2)
R2_23_4 "Res2" 1005[0402] 2815.5,1859 r180 top (schematic designator R2)
R2_23_5 "Res2" 1005[0402] 3165.5,1859 r180 top (schematic designator R2)
R2_23_6 "Res2" 1005[0402] 3515.5,1859 r180 top (schematic designator R2)
R2_23_7 "Res2" 1005[0402] 3865.5,1859 r180 top (schematic designator R2)
R2_23_8 "Res2" 1005[0402] 4215.5,1859 r180 top (schematic designator R2)
R2_23_9 "Res2" 1005[0402] 4565.5,1859 r180 top (schematic designator R2)
R2_23_10 "Res2" 1005[0402] 4915.5,1859 r180 top (schematic designator R2)
R2_23_11 "Res2" 1005[0402] 5265.5,1859 r180 top (schematic designator R2)
R2_23_12 "Res2" 1005[0402] 5615.5,1859 r180 top (schematic designator R2)
R2_23_13 "Res2" 1005[0402] 5965.5,1859 r180 top (schematic designator R2)
R2_23_14 "Res2" 1005[0402] 6315.5,1859 r180 top (schematic designator R2)
R2_23_15 "Res2" 1005[0402] 6665.5,1859 r180 top (schematic designator R2)
R2_32 "Res2" 1005[0402] 1649.5,2639 r90 top (schematic designator R2)
R2_32_1 "Res2" 1005[0402] 2524.5,2639 r90 top (schematic designator R2)
R2_32_2 "Res2" 1005[0402] 3399.5,2639 r90 top (schematic designator R2)
R2_32_3 "Res2" 1005[0402] 4274.5,2639 r90 top (schematic designator R2)
R2_32_4 "Res2" 1005[0402] 5149.5,2639 r90 top (schematic designator R2)
R2_32_5 "Res2" 1005[0402] 6024.5,2639 r90 top (schematic designator R2)
R3_22 "Res2" 1005[0402] 1259.5,1759 r180 top (schematic designator R3)
R3_22_1 "Res2" 1005[0402] 1610.5,1759 r180 top (schematic designator R3)
R3_22_2 "Res2" 1005[0402] 1960.5,1759 r180 top (schematic designator R3)
R3_22_3 "Res2" 1005[0402] 2310.5,1759 r180 top (schematic designator R3)
R3_22_4 "Res2" 1005[0402] 2660.5,1759 r180 top (schematic designator R3)
R3_22_5 "Res2" 1005[0402] 3010.5,1759 r180 top (schematic designator R3)
R3_22_6 "Res2" 1005[0402] 3360.5,1759 r180 top (schematic designator R3)
R3_22_7 "Res2" 1005[0402] 3710.5,1759 r180 top (schematic designator R3)
R3_22_8 "Res2" 1005[0402] 4060.5,1759 r180 top (schematic designator R3)
R3_22_9 "Res2" 1005[0402] 4410.5,1759 r180 top (schematic designator R3)
R3_22_10 "Res2" 1005[0402] 4760.5,1759 r180 top (schematic designator R3)
R3_22_11 "Res2" 1005[0402] 5110.5,1759 r180 top (schematic designator R3)
R3_22_12 "Res2" 1005[0402] 5460.5,1759 r180 top (schematic designator R3)
R3_22_13 "Res2" 1005[0402] 5810.5,1759 r180 top (schematic designator R3)
R3_22_14 "Res2" 1005[0402] 6160.5,1759 r180 top (schematic designator R3)
R3_22_15 "Res2" 1005[0402] 6510.5,1759 r180 top (schematic designator R3)
R3_23 "Res2" 1005[0402] 1434.5,1759 r180 top (schematic designator R3)
R3_23_1 "Res2" 1005[0402] 1785.5,1759 r180 top (schematic designator R3)
R3_23_2 "Res2" 1005[0402] 2135.5,1759 r180 top (schematic designator R3)
R3_23_3 "Res2" 1005[0402] 2485.5,1759 r180 top (schematic designator R3)
R3_23_4 "Res2" 1005[0402] 2835.5,1759 r180 top (schematic designator R3)
R3_23_5 "Res2" 1005[0402] 3185.5,1759 r180 top (schematic designator R3)
R3_23_6 "Res2" 1005[0402] 3535.5,1759 r180 top (schematic designator R3)
R3_23_7 "Res2" 1005[0402] 3885.5,1759 r180 top (schematic designator R3)
R3_23_8 "Res2" 1005[0402] 4235.5,1759 r180 top (schematic designator R3)
R3_23_9 "Res2" 1005[0402] 4585.5,1759 r180 top (schematic designator R3)
R3_23_10 "Res2" 1005[0402] 4935.5,1759 r180 top (schematic designator R3)
R3_23_11 "Res2" 1005[0402] 5285.5,1759 r180 top (schematic designator R3)
R3_23_12 "Res2" 1005[0402] 5635.5,1759 r180 top (schematic designator R3)
R3_23_13 "Res2" 1005[0402] 5985.5,1759 r180 top (schematic designator R3)
R3_23_14 "Res2" 1005[0402] 6335.5,1759 r180 top (schematic designator R3)
R3_23_15 "Res2" 1005[0402] 6685.5,1759 r180 top (schematic designator R3)
R3_32 "Res2" 1005[0402] 1709.5,2639 r90 top (schematic designator R3)
R3_32_1 "Res2" 1005[0402] 2584.5,2639 r90 top (schematic designator R3)
R3_32_2 "Res2" 1005[0402] 3459.5,2639 r90 top (schematic designator R3)
R3_32_3 "Res2" 1005[0402] 4334.5,2639 r90 top (schematic designator R3)
R3_32_4 "Res2" 1005[0402] 5209.5,2639 r90 top (schematic designator R3)
R3_32_5 "Res2" 1005[0402] 6084.5,2639 r90 top (schematic designator R3)
R4_22 "Res2" 1005[0402] 1179.5,1939 r270 top (schematic designator R4)
R4_22_1 "Res2" 1005[0402] 1530.5,1939 r270 top (schematic designator R4)
R4_22_2 "Res2" 1005[0402] 1880.5,1939 r270 top (schematic designator R4)
R4_22_3 "Res2" 1005[0402] 2230.5,1939 r270 top (schematic designator R4)
R4_22_4 "Res2" 1005[0402] 2580.5,1939 r270 top (schematic designator R4)
R4_22_5 "Res2" 1005[0402] 2930.5,1939 r270 top (schematic designator R4)
R4_22_6 "Res2" 1005[0402] 3280.5,1939 r270 top (schematic designator R4)
R4_22_7 "Res2" 1005[0402] 3630.5,1939 r270 top (schematic designator R4)
R4_22_8 "Res2" 1005[0402] 3980.5,1939 r270 top (schematic designator R4)
R4_22_9 "Res2" 1005[0402] 4330.5,1939 r270 top (schematic designator R4)
R4_22_10 "Res2" 1005[0402] 4680.5,1939 r270 top (schematic designator R4)
R4_22_11 "Res2" 1005[0402] 5030.5,1939 r270 top (schematic designator R4)
R4_22_12 "Res2" 1005[0402] 5380.5,1939 r270 top (schematic designator R4)
R4_22_13 "Res2" 1005[0402] 5730.5,1939 r270 top (schematic designator R4)
R4_22_14 "Res2" 1005[0402] 6080.5,1939 r270 top (schematic designator R4)
R4_22_15 "Res2" 1005[0402] 6430.5,1939 r270 top (schematic designator R4)
R4_23 "Res2" 1005[0402] 1354.5,1939 r270 top (schematic designator R4)
R4_23_1 "Res2" 1005[0402] 1705.5,1939 r270 top (schematic designator R4)
R4_23_2 "Res2" 1005[0402] 2055.5,1939 r270 top (schematic designator R4)
R4_23_3 "Res2" 1005[0402] 2405.5,1939 r270 top (schematic designator R4)
R4_23_4 "Res2" 1005[0402] 2755.5,1939 r270 top (schematic designator R4)
R4_23_5 "Res2" 1005[0402] 3105.5,1939 r270 top (schematic designator R4)
R4_23_6 "Res2" 1005[0402] 3455.5,1939 r270 top (schematic designator R4)
R4_23_7 "Res2" 1005[0402] 3805.5,1939 r270 top (schematic designator R4)
R4_23_8 "Res2" 1005[0402] 4155.5,1939 r270 top (schematic designator R4)
R4_23_9 "Res2" 1005[0402] 4505.5,1939 r270 top (schematic designator R4)
R4_23_10 "Res2" 1005[0402] 4855.5,1939 r270 top (schematic designator R4)
R4_23_11 "Res2" 1005[0402] 5205.5,1939 r270 top (schematic designator R4)
R4_23_12 "Res2" 1005[0402] 5555.5,1939 r270 top (schematic designator R4)
R4_23_13 "Res2" 1005[0402] 5905.5,1939 r270 top (schematic designator R4)
R4_23_14 "Res2" 1005[0402] 6255.5,1939 r270 top (schematic designator R4)
R4_23_15 "Res2" 1005[0402] 6605.5,1939 r270 top (schematic designator R4)
R5_22 "Res2" 1005[0402] 1239.5,1701 r180 top (schematic designator R5)
R5_22_1 "Res2" 1005[0402] 1590.5,1701 r180 top (schematic designator R5)
R5_22_2 "Res2" 1005[0402] 1940.5,1701 r180 top (schematic designator R5)
R5_22_3 "Res2" 1005[0402] 2290.5,1701 r180 top (schematic designator R5)
R5_22_4 "Res2" 1005[0402] 2640.5,1701 r180 top (schematic designator R5)
R5_22_5 "Res2" 1005[0402] 2990.5,1701 r180 top (schematic designator R5)
R5_22_6 "Res2" 1005[0402] 3340.5,1701 r180 top (schematic designator R5)
R5_22_7 "Res2" 1005[0402] 3690.5,1701 r180 top (schematic designator R5)
R5_22_8 "Res2" 1005[0402] 4040.5,1701 r180 top (schematic designator R5)
R5_22_9 "Res2" 1005[0402] 4390.5,1701 r180 top (schematic designator R5)
R5_22_10 "Res2" 1005[0402] 4740.5,1701 r180 top (schematic designator R5)
R5_22_11 "Res2" 1005[0402] 5090.5,1701 r180 top (schematic designator R5)
R5_22_12 "Res2" 1005[0402] 5440.5,1701 r180 top (schematic designator R5)
R5_22_13 "Res2" 1005[0402] 5790.5,1701 r180 top (schematic designator R5)
R5_22_14 "Res2" 1005[0402] 6140.5,1701 r180 top (schematic designator R5)
R5_22_15 "Res2" 1005[0402] 6490.5,1701 r180 top (schematic designator R5)
R5_23 "Res2" 1005[0402] 1414.5,1701 r180 top (schematic designator R5)
R5_23_1 "Res2" 1005[0402] 1765.5,1701 r180 top (schematic designator R5)
R5_23_2 "Res2" 1005[0402] 2115.5,1701 r180 top (schematic designator R5)
R5_23_3 "Res2" 1005[0402] 2465.5,1701 r180 top (schematic designator R5)
R5_23_4 "Res2" 1005[0402] 2815.5,1701 r180 top (schematic designator R5)
R5_23_5 "Res2" 1005[0402] 3165.5,1701 r180 top (schematic designator R5)
R5_23_6 "Res2" 1005[0402] 3515.5,1701 r180 top (schematic designator R5)
R5_23_7 "Res2" 1005[0402] 3865.5,1701 r180 top (schematic designator R5)
R5_23_8 "Res2" 1005[0402] 4215.5,1701 r180 top (schematic designator R5)
R5_23_9 "Res2" 1005[0402] 4565.5,1701 r180 top (schematic designator R5)
R5_23_10 "Res2" 1005[0402] 4915.5,1701 r180 top (schematic designator R5)
R5_23_11 "Res2" 1005[0402] 5265.5,1701 r180 top (schematic designator R5)
R5_23_12 "Res2" 1005[0402] 5615.5,1701 r180 top (schematic designator R5)
R5_23_13 "Res2" 1005[0402] 5965.5,1701 r180 top (schematic designator R5)
R5_23_14 "Res2" 1005[0402] 6315.5,1701 r180 top (schematic designator R5)
R5_23_15 "Res2" 1005[0402] 6665.5,1701 r180 top (schematic designator R5)
R6_22 "Res2" 1005[0402] 1199.5,1389 r180 top (schematic designator R6)
R6_22_1 "Res2" 1005[0402] 1550.5,1389 r180 top (schematic designator R6)
R6_22_2 "Res2" 1005[0402] 1900.5,1389 r180 top (schematic designator R6)
R6_22_3 "Res2" 1005[0402] 2250.5,1389 r180 top (schematic designator R6)
R6_22_4 "Res2" 1005[0402] 2600.5,1389 r180 top (schematic designator R6)
R6_22_5 "Res2" 1005[0402] 2950.5,1389 r180 top (schematic designator R6)
R6_22_6 "Res2" 1005[0402] 3300.5,1389 r180 top (schematic designator R6)
R6_22_7 "Res2" 1005[0402] 3650.5,1389 r180 top (schematic designator R6)
R6_22_8 "Res2" 1005[0402] 4000.5,1389 r180 top (schematic designator R6)
R6_22_9 "Res2" 1005[0402] 4350.5,1389 r180 top (schematic designator R6)
R6_22_10 "Res2" 1005[0402] 4700.5,1389 r180 top (schematic designator R6)
R6_22_11 "Res2" 1005[0402] 5050.5,1389 r180 top (schematic designator R6)
R6_22_12 "Res2" 1005[0402] 5400.5,1389 r180 top (schematic designator R6)
R6_22_13 "Res2" 1005[0402] 5750.5,1389 r180 top (schematic designator R6)
R6_22_14 "Res2" 1005[0402] 6100.5,1389 r180 top (schematic designator R6)
R6_22_15 "Res2" 1005[0402] 6450.5,1389 r180 top (schematic designator R6)
R6_23 "Res2" 1005[0402] 1374.5,1389 r180 top (schematic designator R6)
R6_23_1 "Res2" 1005[0402] 1725.5,1389 r180 top (schematic designator R6)
R6_23_2 "Res2" 1005[0402] 2075.5,1389 r180 top (schematic designator R6)
R6_23_3 "Res2" 1005[0402] 2425.5,1389 r180 top (schematic designator R6)
R6_23_4 "Res2" 1005[0402] 2775.5,1389 r180 top (schematic designator R6)
R6_23_5 "Res2" 1005[0402] 3125.5,1389 r180 top (schematic designator R6)
R6_23_6 "Res2" 1005[0402] 3475.5,1389 r180 top (schematic designator R6)
R6_23_7 "Res2" 1005[0402] 3825.5,1389 r180 top (schematic designator R6)
R6_23_8 "Res2" 1005[0402] 4175.5,1389 r180 top (schematic designator R6)
R6_23_9 "Res2" 1005[0402] 4525.5,1389 r180 top (schematic designator R6)
R6_23_10 "Res2" 1005[0402] 4875.5,1389 r180 top (schematic designator R6)
R6_23_11 "Res2" 1005[0402] 5225.5,1389 r180 top (schematic designator R6)
R6_23_12 "Res2" 1005[0402] 5575.5,1389 r180 top (schematic designator R6)
R6_23_13 "Res2" 1005[0402] 5925.5,1389 r180 top (schematic designator R6)
R6_23_14 "Res2" 1005[0402] 6275.5,1389 r180 top (schematic designator R6)
R6_23_15 "Res2" 1005[0402] 6625.5,1389 r180 top (schematic designator R6)
R7_22 "Res2" 1005[0402] 1217.5,2228 r0 top (schematic designator R7)
R7_22_1 "Res2" 1005[0402] 1568.5,2228 r0 top (schematic designator R7)
R7_22_2 "Res2" 1005[0402] 1918.5,2228 r0 top (schematic designator R7)
R7_22_3 "Res2" 1005[0402] 2268.5,2228 r0 top (schematic designator R7)
R7_22_4 "Res2" 1005[0402] 2618.5,2228 r0 top (schematic designator R7)
R7_22_5 "Res2" 1005[0402] 2968.5,2228 r0 top (schematic designator R7)
R7_22_6 "Res2" 1005[0402] 3318.5,2228 r0 top (schematic designator R7)
R7_22_7 "Res2" 1005[0402] 3668.5,2228 r0 top (schematic designator R7)
R7_22_8 "Res2" 1005[0402] 4018.5,2228 r0 top (schematic designator R7)
R7_22_9 "Res2" 1005[0402] 4368.5,2228 r0 top (schematic designator R7)
R7_22_10 "Res2" 1005[0402] 4718.5,2228 r0 top (schematic designator R7)
R7_22_11 "Res2" 1005[0402] 5068.5,2228 r0 top (schematic designator R7)
R7_22_12 "Res2" 1005[0402] 5418.5,2228 r0 top (schematic designator R7)
R7_22_13 "Res2" 1005[0402] 5768.5,2228 r0 top (schematic designator R7)
R7_22_14 "Res2" 1005[0402] 6118.5,2228 r0 top (schematic designator R7)
R7_22_15 "Res2" 1005[0402] 6468.5,2228 r0 top (schematic designator R7)
R7_23 "Res2" 1005[0402] 1396.5,2234 r0 top (schematic designator R7)
R7_23_1 "Res2" 1005[0402] 1747.5,2234 r0 top (schematic designator R7)
R7_23_2 "Res2" 1005[0402] 2097.5,2234 r0 top (schematic designator R7)
R7_23_3 "Res2" 1005[0402] 2447.5,2234 r0 top (schematic designator R7)
R7_23_4 "Res2" 1005[0402] 2797.5,2234 r0 top (schematic designator R7)
R7_23_5 "Res2" 1005[0402] 3147.5,2234 r0 top (schematic designator R7)
R7_23_6 "Res2" 1005[0402] 3497.5,2234 r0 top (schematic designator R7)
R7_23_7 "Res2" 1005[0402] 3847.5,2234 r0 top (schematic designator R7)
R7_23_8 "Res2" 1005[0402] 4197.5,2234 r0 top (schematic designator R7)
R7_23_9 "Res2" 1005[0402] 4547.5,2234 r0 top (schematic designator R7)
R7_23_10 "Res2" 1005[0402] 4897.5,2234 r0 top (schematic designator R7)
R7_23_11 "Res2" 1005[0402] 5247.5,2234 r0 top (schematic designator R7)
R7_23_12 "Res2" 1005[0402] 5597.5,2234 r0 top (schematic designator R7)
R7_23_13 "Res2" 1005[0402] 5947.5,2234 r0 top (schematic designator R7)
R7_23_14 "Res2" 1005[0402] 6297.5,2234 r0 top (schematic designator R7)
R7_23_15 "Res2" 1005[0402] 6647.5,2234 r0 top (schematic designator R7)
R8_22 "Res2" 1005[0402] 1259.5,1489 r0 top (schematic designator R8)
R8_22_1 "Res2" 1005[0402] 1610.5,1489 r0 top (schematic designator R8)
R8_22_2 "Res2" 1005[0402] 1960.5,1489 r0 top (schematic designator R8)
R8_22_3 "Res2" 1005[0402] 2310.5,1489 r0 top (schematic designator R8)
R8_22_4 "Res2" 1005[0402] 2660.5,1489 r0 top (schematic designator R8)
R8_22_5 "Res2" 1005[0402] 3010.5,1489 r0 top (schematic designator R8)
R8_22_6 "Res2" 1005[0402] 3360.5,1489 r0 top (schematic designator R8)
R8_22_7 "Res2" 1005[0402] 3710.5,1489 r0 top (schematic designator R8)
R8_22_8 "Res2" 1005[0402] 4060.5,1489 r0 top (schematic designator R8)
R8_22_9 "Res2" 1005[0402] 4410.5,1489 r0 top (schematic designator R8)
R8_22_10 "Res2" 1005[0402] 4760.5,1489 r0 top (schematic designator R8)
R8_22_11 "Res2" 1005[0402] 5110.5,1489 r0 top (schematic designator R8)
R8_22_12 "Res2" 1005[0402] 5460.5,1489 r0 top (schematic designator R8)
R8_22_13 "Res2" 1005[0402] 5810.5,1489 r0 top (schematic designator R8)
R8_22_14 "Res2" 1005[0402] 6160.5,1489 r0 top (schematic designator R8)
R8_22_15 "Res2" 1005[0402] 6510.5,1489 r0 top (schematic designator R8)
R8_23 "Res2" 1005[0402] 1434.5,1489 r0 top (schematic designator R8)
R8_23_1 "Res2" 1005[0402] 1785.5,1489 r0 top (schematic designator R8)
R8_23_2 "Res2" 1005[0402] 2135.5,1489 r0 top (schematic designator R8)
R8_23_3 "Res2" 1005[0402] 2485.5,1489 r0 top (schematic designator R8)
R8_23_4 "Res2" 1005[0402] 2835.5,1489 r0 top (schematic designator R8)
R8_23_5 "Res2" 1005[0402] 3185.5,1489 r0 top (schematic designator R8)
R8_23_6 "Res2" 1005[0402] 3535.5,1489 r0 top (schematic designator R8)
R8_23_7 "Res2" 1005[0402] 3885.5,1489 r0 top (schematic designator R8)
R8_23_8 "Res2" 1005[0402] 4235.5,1489 r0 top (schematic designator R8)
R8_23_9 "Res2" 1005[0402] 4585.5,1489 r0 top (schematic designator R8)
R8_23_10 "Res2" 1005[0402] 4935.5,1489 r0 top (schematic designator R8)
R8_23_11 "Res2" 1005[0402] 5285.5,1489 r0 top (schematic designator R8)
R8_23_12 "Res2" 1005[0402] 5635.5,1489 r0 top (schematic designator R8)
R8_23_13 "Res2" 1005[0402] 5985.5,1489 r0 top (schematic designator R8)
R8_23_14 "Res2" 1005[0402] 6335.5,1489 r0 top (schematic designator R8)
R8_23_15 "Res2" 1005[0402] 6685.5,1489 r0 top (schematic designator R8)
R9_22 "Res2" 1005[0402] 1219.5,2479 r0 top (schematic designator R9)
R9_22_1 "Res2" 1005[0402] 1570.5,2479 r0 top (schematic designator R9)
R9_22_2 "Res2" 1005[0402] 1920.5,2479 r0 top (schematic designator R9)
R9_22_3 "Res2" 1005[0402] 2270.5,2479 r0 top (schematic designator R9)
R9_22_4 "Res2" 1005[0402] 2620.5,2479 r0 top (schematic designator R9)
R9_22_5 "Res2" 1005[0402] 2970.5,2479 r0 top (schematic designator R9)
R9_22_6 "Res2" 1005[0402] 3320.5,2479 r0 top (schematic designator R9)
R9_22_7 "Res2" 1005[0402] 3670.5,2479 r0 top (schematic designator R9)
R9_22_8 "Res2" 1005[0402] 4020.5,2479 r0 top (schematic designator R9)
R9_22_9 "Res2" 1005[0402] 4370.5,2479 r0 top (schematic designator R9)
R9_22_10 "Res2" 1005[0402] 4720.5,2479 r0 top (schematic designator R9)
R9_22_11 "Res2" 1005[0402] 5070.5,2479 r0 top (schematic designator R9)
R9_22_12 "Res2" 1005[0402] 5420.5,2479 r0 top (schematic designator R9)
R9_22_13 "Res2" 1005[0402] 5770.5,2479 r0 top (schematic designator R9)
R9_22_14 "Res2" 1005[0402] 6120.5,2479 r0 top (schematic designator R9)
R9_22_15 "Res2" 1005[0402] 6470.5,2479 r0 top (schematic designator R9)
R9_23 "Res2" 1005[0402] 1394.5,2479 r0 top (schematic designator R9)
R9_23_1 "Res2" 1005[0402] 1745.5,2479 r0 top (schematic designator R9)
R9_23_2 "Res2" 1005[0402] 2095.5,2479 r0 top (schematic designator R9)
R9_23_3 "Res2" 1005[0402] 2445.5,2479 r0 top (schematic designator R9)
R9_23_4 "Res2" 1005[0402] 2795.5,2479 r0 top (schematic designator R9)
R9_23_5 "Res2" 1005[0402] 3145.5,2479 r0 top (schematic designator R9)
R9_23_6 "Res2" 1005[0402] 3495.5,2479 r0 top (schematic designator R9)
R9_23_7 "Res2" 1005[0402] 3845.5,2479 r0 top (schematic designator R9)
R9_23_8 "Res2" 1005[0402] 4195.5,2479 r0 top (schematic designator R9)
R9_23_9 "Res2" 1005[0402] 4545.5,2479 r0 top (schematic designator R9)
R9_23_10 "Res2" 1005[0402] 4895.5,2479 r0 top (schematic designator R9)
R9_23_11 "Res2" 1005[0402] 5245.5,2479 r0 top (schematic designator R9)
R9_23_12 "Res2" 1005[0402] 5595.5,2479 r0 top (schematic designator R9)
R9_23_13 "Res2" 1005[0402] 5945.5,2479 r0 top (schematic designator R9)
R9_23_14 "Res2" 1005[0402] 6295.5,2479 r0 top (schematic designator R9)
R9_23_15 "Res2" 1005[0402] 6645.5,2479 r0 top (schematic designator R9)

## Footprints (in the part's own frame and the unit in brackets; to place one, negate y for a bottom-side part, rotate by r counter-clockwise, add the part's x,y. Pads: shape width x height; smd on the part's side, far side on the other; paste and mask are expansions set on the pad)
0402 [mm] "Chip Capacitor; Body 1.0 x 0.5 mm (LxW typ)"
  rect 0.9x0.7 smd: 1(-0.65,0) 2(0.65,0)
  silkscreen extent -1.4,-0.25 -1.4,0.25
1005[0402] [mm] "Chip Resistor; Body 1.1 x 0.5 mm (LxW typ)"
  rect 0.9x0.7 smd: 1(-0.65,0) 2(0.65,0)
EURO2.54-2H96 [mm] "Connector; DIN 41612, Type C, Thru-Hole; Rows a+b+c, 96 Position; Right Angle"
  round 4.6 hole 2.8: 33(-44.45,-10.1) 34(44.45,-10.1)
  rect 1.575x1.575 hole 1: A1(-39.37,-12.64)
  round 1.575 hole 1: A2(-36.83,-12.64) A3(-34.29,-12.64) A4(-31.75,-12.64) A5(-29.21,-12.64) A6(-26.67,-12.64) A7(-24.13,-12.64) A8(-21.59,-12.64) A9(-19.05,-12.64) A10(-16.51,-12.64) A11(-13.97,-12.64) A12(-11.43,-12.64) A13(-8.89,-12.64) A14(-6.35,-12.64) A15(-3.81,-12.64) A16(-1.27,-12.64) A17(1.27,-12.64) A18(3.81,-12.64) A19(6.35,-12.64) A20(8.89,-12.64) A21(11.43,-12.64) A22(13.97,-12.64) A23(16.51,-12.64) A24(19.05,-12.64) A25(21.59,-12.64) A26(24.13,-12.64) A27(26.67,-12.64) A28(29.21,-12.64) A29(31.75,-12.64) A30(34.29,-12.64) A31(36.83,-12.64) A32(39.37,-12.64) B1(-39.37,-15.18) B2(-36.83,-15.18) B3(-34.29,-15.18) B4(-31.75,-15.18) B5(-29.21,-15.18) B6(-26.67,-15.18) B7(-24.13,-15.18) B8(-21.59,-15.18) B9(-19.05,-15.18) B10(-16.51,-15.18) B11(-13.97,-15.18) B12(-11.43,-15.18) B13(-8.89,-15.18) B14(-6.35,-15.18) B15(-3.81,-15.18) B16(-1.27,-15.18) B17(1.27,-15.18) B18(3.81,-15.18) B19(6.35,-15.18) B20(8.89,-15.18) B21(11.43,-15.18) B22(13.97,-15.18) B23(16.51,-15.18) B24(19.05,-15.18) B25(21.59,-15.18) B26(24.13,-15.18) B27(26.67,-15.18) B28(29.21,-15.18) B29(31.75,-15.18) B30(34.29,-15.18) B31(36.83,-15.18) B32(39.37,-15.18) C1(-39.37,-17.72) C2(-36.83,-17.72) C3(-34.29,-17.72) C4(-31.75,-17.72) C5(-29.21,-17.72) C6(-26.67,-17.72) C7(-24.13,-17.72) C8(-21.59,-17.72) C9(-19.05,-17.72) C10(-16.51,-17.72) C11(-13.97,-17.72) C12(-11.43,-17.72) C13(-8.89,-17.72) C14(-6.35,-17.72) C15(-3.81,-17.72) C16(-1.27,-17.72) C17(1.27,-17.72) C18(3.81,-17.72) C19(6.35,-17.72) C20(8.89,-17.72) C21(11.43,-17.72) C22(13.97,-17.72) C23(16.51,-17.72) C24(19.05,-17.72) C25(21.59,-17.72) C26(24.13,-17.72) C27(26.67,-17.72) C28(29.21,-17.72) C29(31.75,-17.72) C30(34.29,-17.72) C31(36.83,-17.72) C32(39.37,-17.72)
  silkscreen extent -47,-13.14 47,0
"Photonique SiPM" [mil] "Photosensitive Diode; 2 Leads"
  round 40 hole 19.7: 1(-50,50) 2(50,50)
SOT23_N [mm] "SOT23, 3-Leads, Body 2.9x1.3mm, Pitch 0.95mm, Lead Span 2.3mm, IPC Medium Density"
  rect 1.3x0.6 smd: 1(-1.05,0.95) 2(-1.05,-0.95) 3(1.05,0)
  silkscreen extent -1.17,-1.5 0.7,1.93, body extent -0.7,-1.5 0.7,1.5, height 1.1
